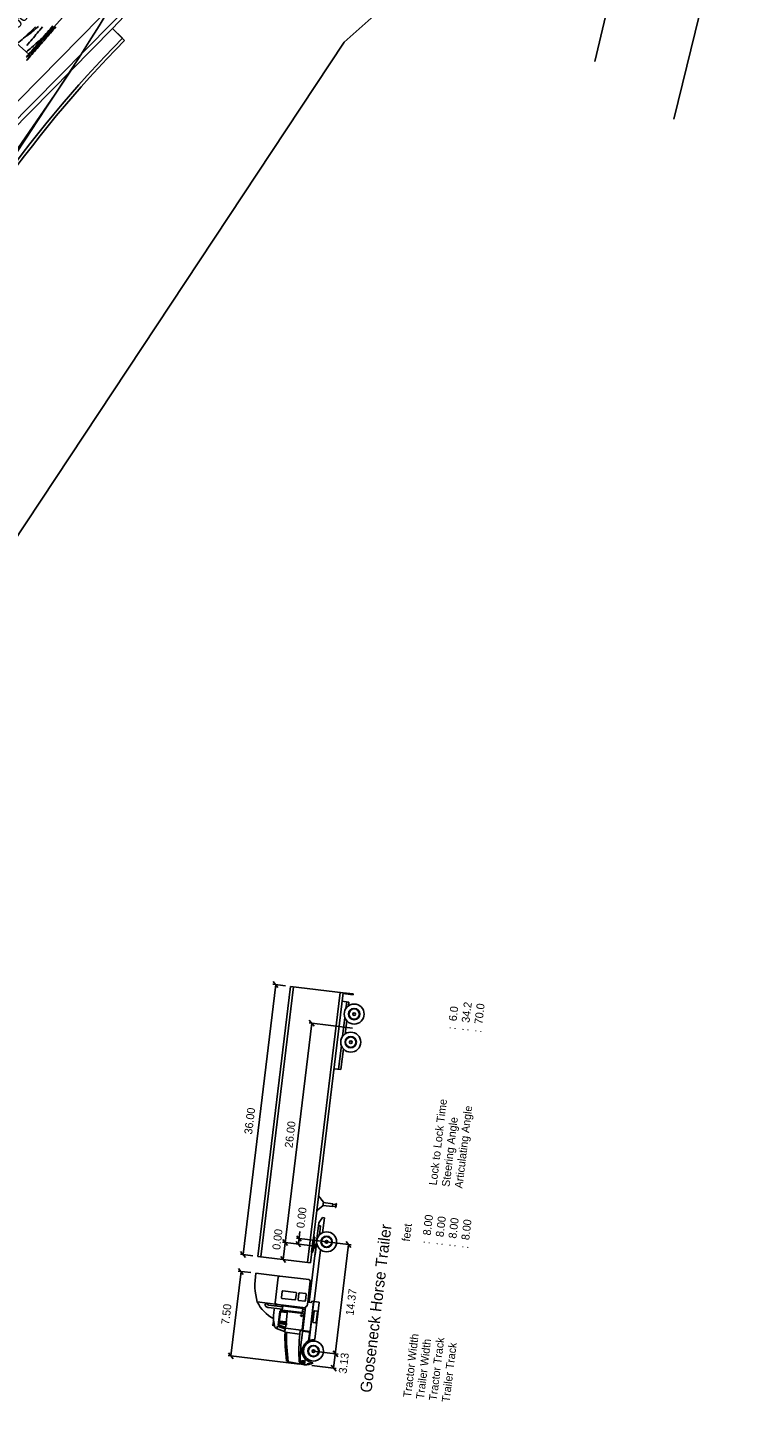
# Model space of a CAD drawing. Extents: x -14 to 1565148, y -25 to 642856.
# Drawn here: x 1564862.1 to 1564980.6, y 636183.8 to 636409.1 of the extents above; entities that cross this region are included whole.
import ezdxf

# ---------------------------------------------------------------- set-up
doc = ezdxf.new("R2010")
doc.units = 0
for name, color, linetype in [('DR_P_Erosion_Control', 7, 'Continuous'), ('DR_P_Headwall', 7, 'Continuous'), ('GE_X_Alignment', 7, 'Continuous'), ('MT_P_Drums', 7, 'Continuous'), ('PF_P_Grade_Line', 7, 'Continuous'), ('PM_P_Edge_Line', 7, 'Continuous'), ('PV_P_EOP', 7, 'Continuous'), ('PV_P_Saw_Cut_Line', 7, 'Continuous'), ('PV_X_EOP', 7, 'Continuous'), ('SC_Scratch2', 7, 'Continuous'), ('TR_Turning_Path23', 7, 'Continuous'), ('TR_Turning_Path25', 7, 'Continuous'), ('TR_Turning_Path27', 7, 'Continuous'), ('TR_Turning_Path28', 7, 'Continuous')]:
    doc.layers.add(name, color=color, linetype=linetype)

msp = doc.modelspace()

# ---------------------------------------------------------------- linework, layer by layer
at = {"layer": 'DR_P_Erosion_Control'}
for points in [[(1564881.8, 636423.67), (1564881.06, 636422.17), (1564879.75, 636419.64), (1564878.38, 636417.1), (1564876.93, 636414.54), (1564875.42, 636411.96), (1564873.86, 636409.38), (1564872.24, 636406.8), (1564870.59, 636404.2), (1564868.91, 636401.61), (1564867.2, 636399.01), (1564865.44, 636396.36), (1564863.66, 636393.67), (1564861.88, 636390.97), (1564860.09, 636388.25), (1564858.31, 636385.51), (1564857.43, 636384.14)], [(1564869.82, 636402.93), (1564868.42, 636400.82), (1564866.64, 636398.18), (1564864.84, 636395.55), (1564863.03, 636392.92), (1564861.23, 636390.3), (1564859.44, 636387.7), (1564857.68, 636385.12), (1564855.93, 636382.52), (1564854.2, 636379.89), (1564852.49, 636377.24), (1564851.99, 636376.44)]]:
    msp.add_lwpolyline(points, dxfattribs=at)
at = {"layer": 'DR_P_Headwall'}
msp.add_line((1564968.16, 636394.09), (1564980.6, 636444.84), dxfattribs=at)
at = {"layer": 'GE_X_Alignment'}
msp.add_lwpolyline([(1564859.34, 636391.97), (1564876.08, 636408.94), (1564877.69, 636407.36)], dxfattribs=at)
msp.add_arc((1565016.49, 636270.39), 195, 135.3822, 155.0629, dxfattribs=at)
at = {"layer": 'MT_P_Drums'}
for points in [[(1564860.2, 636406.31), (1564860.45, 636406.51), (1564860.71, 636406.73), (1564860.97, 636406.94), (1564861.22, 636407.16), (1564861.48, 636407.38), (1564861.73, 636407.61), (1564861.98, 636407.83), (1564862.23, 636408.06), (1564862.48, 636408.3), (1564862.72, 636408.53), (1564862.97, 636408.77), (1564863.2, 636409.01), (1564863.44, 636409.25)], [(1564861.94, 636404.32), (1564862.16, 636404.57), (1564862.38, 636404.82), (1564862.59, 636405.07), (1564862.81, 636405.32), (1564863.03, 636405.58), (1564863.24, 636405.83), (1564863.46, 636406.08), (1564863.68, 636406.33), (1564863.89, 636406.59), (1564864.11, 636406.84), (1564864.33, 636407.09), (1564864.55, 636407.35), (1564864.76, 636407.6), (1564864.98, 636407.85), (1564865.2, 636408.11), (1564865.41, 636408.36), (1564865.63, 636408.61), (1564865.85, 636408.87), (1564866.06, 636409.12), (1564866.28, 636409.38)]]:
    msp.add_lwpolyline(points, dxfattribs=at)
at = {"layer": 'PF_P_Grade_Line'}
for p, q in [((1564902.84, 636252.15), (1564897.48, 636207.86)), ((1564905.28, 636251.85), (1564899.92, 636207.57)), ((1564905.74, 636251.8), (1564900.38, 636207.51)), ((1564904.46, 636251.95), (1564902.4, 636252.2)), ((1564903.22, 636251.66), (1564902.45, 636252.64)), ((1564913.89, 636250.81), (1564905.28, 636251.85)), ((1564908.07, 636206.58), (1564913.43, 636250.87)), ((1564908.53, 636206.53), (1564913.89, 636250.81)), ((1564914.87, 636249.28), (1564913.72, 636249.42)), ((1564915.56, 636250.45), (1564913.87, 636250.66)), ((1564913.89, 636250.81), (1564915.58, 636250.61)), ((1564914.36, 636248.22), (1564914.49, 636249.32)), ((1564914.8, 636248.67), (1564914.87, 636249.28)), ((1564915.58, 636250.61), (1564915.56, 636250.45)), ((1564913.8, 636243.61), (1564914.18, 636246.76)), ((1564908.75, 636245.82), (1564904.06, 636207.07)), ((1564908.31, 636245.87), (1564915.44, 636245.01)), ((1564909.13, 636245.32), (1564908.36, 636246.31)), ((1564914.24, 636244.06), (1564914.5, 636246.22)), ((1564913.15, 636238.25), (1564913.62, 636242.15)), ((1564913.54, 636238.21), (1564913.95, 636241.6)), ((1564913.54, 636238.21), (1564912.38, 636238.35)), ((1564910.67, 636216.47), (1564909.86, 636217.5)), ((1564910.6, 636215.85), (1564909.56, 636215.04)), ((1564910.6, 636215.85), (1564910.67, 636216.47)), ((1564912.15, 636215.74), (1564910.61, 636215.93)), ((1564912.2, 636216.2), (1564910.66, 636216.39)), ((1564912.15, 636215.74), (1564912.2, 636216.2)), ((1564912.67, 636215.76), (1564912.15, 636215.82)), ((1564912.71, 636216.06), (1564912.19, 636216.13)), ((1564912.65, 636215.6), (1564912.72, 636216.22)), ((1564912.73, 636215.59), (1564912.65, 636215.6)), ((1564912.8, 636216.21), (1564912.72, 636216.22)), ((1564912.73, 636215.59), (1564912.8, 636216.21)), ((1564908.36, 636200.04), (1564909.94, 636213.09)), ((1564909.94, 636213.09), (1564910.54, 636213.94)), ((1564910.53, 636211.44), (1564910.83, 636213.9)), ((1564910.83, 636213.9), (1564910.54, 636213.94)), ((1564906.23, 636210.55), (1564915.25, 636209.46)), ((1564907.03, 636210.05), (1564906.32, 636210.94)), ((1564906.56, 636209.57), (1564906.81, 636211.65)), ((1564908.96, 636210.06), (1564909.22, 636210.73)), ((1564909.12, 636209.54), (1564909.26, 636210.72)), ((1564909.31, 636207.84), (1564909.64, 636210.61)), ((1564909.88, 636212.6), (1564910.19, 636212.57)), ((1564910.01, 636211.07), (1564910.19, 636212.57)), ((1564897.87, 636207.37), (1564897.09, 636208.36)), ((1564908.87, 636209.29), (1564903.95, 636209.89)), ((1564904.78, 636209.34), (1564904.01, 636210.33)), ((1564906.91, 636209.12), (1564906.21, 636210.02)), ((1564908.74, 636208.25), (1564908.96, 636210.06)), ((1564908.86, 636209.22), (1564908.99, 636209.2)), ((1564908.88, 636209.37), (1564909.01, 636209.36)), ((1564908.96, 636208.23), (1564909.05, 636209)), ((1564908.99, 636209.2), (1564909.01, 636209.36)), ((1564909.18, 636209.02), (1564909.12, 636209.11)), ((1564909.24, 636209.49), (1564909.16, 636209.41)), ((1564909.17, 636200.17), (1564910.2, 636208.66)), ((1564909.18, 636209), (1564909.2, 636209.16)), ((1564909.42, 636208.79), (1564909.19, 636208.97)), ((1564909.24, 636209.51), (1564909.22, 636209.34)), ((1564909.53, 636209.65), (1564909.26, 636209.54)), ((1564912.35, 636189.22), (1564914.81, 636209.51)), ((1564915.2, 636209.02), (1564914.42, 636210.01)), ((1564899.11, 636207.67), (1564897.04, 636207.92)), ((1564908.53, 636206.53), (1564899.92, 636207.57)), ((1564904.45, 636206.58), (1564903.67, 636207.56)), ((1564908.74, 636208.25), (1564908.96, 636208.23)), ((1564897.15, 636205.1), (1564895.47, 636191.26)), ((1564898.77, 636204.9), (1564896.71, 636205.15)), ((1564897.53, 636204.6), (1564896.76, 636205.59)), ((1564903.51, 636204.33), (1564899.6, 636204.8)), ((1564902.75, 636199.97), (1564903.25, 636204.13)), ((1564903.51, 636204.33), (1564908.31, 636203.75)), ((1564903.77, 636200.81), (1564903.89, 636201.82)), ((1564906.14, 636201.66), (1564904.01, 636201.92)), ((1564906.12, 636200.52), (1564906.24, 636201.54)), ((1564907.77, 636201.46), (1564906.76, 636201.58)), ((1564908.1, 636200.07), (1564908.51, 636203.49)), ((1564903.22, 636199.68), (1564899.82, 636200.09)), ((1564901.48, 636199.76), (1564901.09, 636199.81)), ((1564903.97, 636199.28), (1564901.72, 636199.55)), ((1564903.22, 636199.68), (1564902.95, 636199.71)), ((1564903.22, 636199.68), (1564907.73, 636199.14)), ((1564903.74, 636199.31), (1564903.78, 636199.61)), ((1564905.99, 636200.43), (1564903.86, 636200.68)), ((1564903.91, 636198.74), (1564903.99, 636199.43)), ((1564907.28, 636199.03), (1564903.99, 636199.43)), ((1564906.51, 636200.47), (1564906.63, 636201.49)), ((1564907.62, 636200.23), (1564906.61, 636200.35)), ((1564907.75, 636199.28), (1564907.28, 636195.39)), ((1564907.73, 636199.14), (1564907.75, 636199.28)), ((1564907.74, 636200.32), (1564907.87, 636201.34)), ((1564907.87, 636199.37), (1564907.9, 636199.37)), ((1564908.02, 636199.46), (1564908.1, 636200.07)), ((1564908.1, 636200.07), (1564908.63, 636200)), ((1564908.34, 636193.77), (1564909.12, 636200.18)), ((1564908.48, 636195.29), (1564909.07, 636200.18)), ((1564908.78, 636200.12), (1564908.8, 636200.22)), ((1564908.8, 636200.22), (1564909.94, 636200.08)), ((1564909.27, 636193.98), (1564910, 636200)), ((1564903.93, 636198.89), (1564901.68, 636199.17)), ((1564902.4, 636197.16), (1564902.49, 636197.15)), ((1564902.49, 636197.08), (1564902.4, 636197.16)), ((1564902.41, 636196.43), (1564902.49, 636197.08)), ((1564903.25, 636196.36), (1564903.51, 636198.5)), ((1564903.37, 636196.39), (1564903.62, 636198.43)), ((1564903.66, 636198.62), (1564903.7, 636198.92)), ((1564907.36, 636198.17), (1564903.66, 636198.62)), ((1564904.68, 636198.37), (1564903.7, 636198.49)), ((1564907.2, 636198.34), (1564903.91, 636198.74)), ((1564904.48, 636196.01), (1564904.75, 636198.29)), ((1564907.02, 636197.97), (1564906.91, 636197.87)), ((1564907, 636197.74), (1564906.91, 636197.87)), ((1564907, 636197.74), (1564907.02, 636197.97)), ((1564907.21, 636197.72), (1564907, 636197.74)), ((1564907.23, 636197.95), (1564907.02, 636197.97)), ((1564907.18, 636195.6), (1564907.48, 636198.02)), ((1564907.2, 636198.34), (1564907.28, 636199.03)), ((1564907.21, 636197.72), (1564907.23, 636197.95)), ((1564907.65, 636198.44), (1564907.22, 636198.5)), ((1564907.69, 636198.83), (1564907.26, 636198.88)), ((1564908.93, 636196.78), (1564909.14, 636198.57)), ((1564909.62, 636198.58), (1564909.22, 636198.63)), ((1564909.46, 636196.71), (1564909.68, 636198.5)), ((1564902.28, 636196.31), (1564902.41, 636196.43)), ((1564902.55, 636196.27), (1564902.28, 636196.31)), ((1564902.49, 636196.42), (1564902.53, 636196.78)), ((1564902.56, 636196.32), (1564902.49, 636196.42)), ((1564902.54, 636196.16), (1564902.58, 636196.51)), ((1564902.67, 636196.14), (1564902.54, 636196.16)), ((1564902.95, 636195.76), (1564902.91, 636195.77)), ((1564904.29, 636195.25), (1564902.95, 636195.76)), ((1564903.04, 636195.72), (1564903.14, 636196.12)), ((1564904.34, 636195.67), (1564903.14, 636196.12)), ((1564903.31, 636196.44), (1564903.35, 636196.76)), ((1564903.34, 636196.43), (1564903.31, 636196.44)), ((1564903.34, 636196.43), (1564903.38, 636196.76)), ((1564904.45, 636195.79), (1564903.34, 636196.21)), ((1564903.39, 636196.56), (1564904.53, 636196.42)), ((1564904.37, 636195.95), (1564903.42, 636196.31)), ((1564903.46, 636196.83), (1564904.54, 636196.7)), ((1564903.47, 636196.85), (1564904.54, 636196.72)), ((1564903.49, 636196.71), (1564903.52, 636196.95)), ((1564904.47, 636196.59), (1564903.49, 636196.71)), ((1564903.52, 636196.95), (1564904.5, 636196.83)), ((1564904.29, 636195.25), (1564904.38, 636195.58)), ((1564904.34, 636195.67), (1564904.39, 636195.81)), ((1564904.38, 636195.12), (1564906.75, 636194.83)), ((1564904.45, 636195.79), (1564907.03, 636195.48)), ((1564904.5, 636196.83), (1564904.47, 636196.59)), ((1564904.61, 636196.61), (1564904.57, 636196.29)), ((1564904.59, 636196.28), (1564904.57, 636196.29)), ((1564904.63, 636196.61), (1564904.59, 636196.28)), ((1564906.83, 636194.89), (1564906.88, 636195.37)), ((1564906.96, 636195.43), (1564907.28, 636195.39)), ((1564907.27, 636195.3), (1564908.42, 636195.16)), ((1564907.28, 636195.39), (1564908.43, 636195.25)), ((1564908.25, 636193.72), (1564908.43, 636195.25)), ((1564909.39, 636196.65), (1564908.99, 636196.7)), ((1564906.76, 636189.89), (1564895.03, 636191.31)), ((1564895.86, 636190.77), (1564895.09, 636191.75)), ((1564907.57, 636189.79), (1564904.74, 636190.32)), ((1564906.87, 636190.08), (1564906.96, 636190.31)), ((1564906.96, 636190.31), (1564907.47, 636190.13)), ((1564907.44, 636189.86), (1564907.5, 636190.37)), ((1564907.57, 636189.79), (1564907.68, 636190.7)), ((1564909.07, 636192.03), (1564913.08, 636191.55)), ((1564913.03, 636191.11), (1564912.26, 636192.09)), ((1564908, 636189.79), (1564908.02, 636189.93)), ((1564908.02, 636189.93), (1564908.47, 636190.02)), ((1564908.45, 636189.87), (1564908.47, 636190.02)), ((1564908.78, 636189.65), (1564912.79, 636189.16)), ((1564912.74, 636188.72), (1564911.97, 636189.71))]:
    msp.add_line(p, q, dxfattribs=at)
for centre, radius in [((1564915.72, 636247.31), 1.64), ((1564915.72, 636247.31), 0.929), ((1564915.72, 636247.31), 0.852), ((1564915.72, 636247.31), 0.223), ((1564915.16, 636242.7), 1.64), ((1564915.16, 636242.7), 0.929), ((1564915.16, 636242.7), 0.852), ((1564915.16, 636242.7), 0.223), ((1564911.2, 636209.95), 1.64), ((1564911.2, 636209.95), 0.929), ((1564911.2, 636209.95), 0.852), ((1564909.08, 636209.27), 0.0483), ((1564911.2, 636209.95), 0.223), ((1564909.04, 636192.04), 1.64), ((1564909.04, 636192.04), 0.929), ((1564909.04, 636192.04), 0.852), ((1564909.04, 636192.04), 0.223)]:
    msp.add_circle(centre, radius, dxfattribs=at)
for centre, radius, start, end in [((1564909.24, 636210.7), 0.0343, 44.2496, 121.9601), ((1564909.21, 636208.98), 0.155, 113.1048, 173.1048), ((1564909.27, 636209.52), 0.155, 173.1048, 233.1048), ((1564909.08, 636209.27), 0.155, 293.1048, 53.1048), ((1564909.22, 636209), 0.0387, 173.1048, 233.1048), ((1564909.28, 636209.5), 0.0387, 113.1048, 173.1048), ((1564909.87, 636202.92), 10.44, 169.6193, 195.7684), ((1564903.48, 636204.1), 0.232, 83.1048, 173.1048), ((1564904, 636201.81), 0.109, 83.1048, 173.1048), ((1564906.13, 636201.55), 0.109, 353.1048, 83.1048), ((1564906.74, 636201.48), 0.109, 83.1048, 173.1048), ((1564908.28, 636203.52), 0.232, 353.1048, 83.1048), ((1564905.14, 636202.66), 5.91, 205.8307, 243.2028), ((1564901.7, 636199.78), 0.614, 177.4065, 267.4065), ((1564901.81, 636199.91), 0.369, 203.6157, 255.7447), ((1564902.98, 636199.94), 0.232, 173.1048, 263.1048), ((1564903.17, 636199.22), 0.465, 83.1048, 153.7642), ((1564903.88, 636200.79), 0.109, 173.1048, 263.1048), ((1564906.01, 636200.53), 0.109, 263.1048, 353.1048), ((1564906.62, 636200.46), 0.109, 173.1048, 263.1048), ((1564907.64, 636200.34), 0.109, 263.1048, 353.1048), ((1564907.86, 636199.27), 0.109, 83.1048, 173.1048), ((1564907.76, 636201.35), 0.109, 353.1048, 83.1048), ((1564907.91, 636199.48), 0.109, 263.1048, 353.1048), ((1564908.65, 636200.14), 0.136, 263.1048, 353.1048), ((1564909.93, 636200.01), 0.0682, 353.1048, 83.1048), ((1564907.52, 636197.52), 5.04, 171.3705, 197.9534), ((1564907.17, 636198.03), 4.64, 167.3148, 176.9795), ((1564903.64, 636198.48), 0.136, 83.1048, 173.1048), ((1564903.69, 636198.42), 0.0774, 83.1048, 173.1048), ((1564904.67, 636198.3), 0.0774, 353.1048, 83.1048), ((1564906.91, 636197.87), 0.00545, 83.1048, 263.1048), ((1564906.91, 636197.87), 0.00545, 263.1048, 83.1048), ((1564907.34, 636198.03), 0.136, 353.1048, 83.1048), ((1564909.21, 636198.56), 0.0682, 83.1048, 173.1048), ((1564909.61, 636198.51), 0.0682, 353.1048, 83.1048), ((1564902.61, 636196.2), 0.0826, 210.2016, 316.008), ((1564903.02, 636196.06), 0.31, 197.9534, 249.2351), ((1564903.39, 636196.34), 0.136, 173.1048, 249.2351), ((1564903.45, 636196.75), 0.101, 83.1048, 173.1048), ((1564903.45, 636196.38), 0.0774, 173.1048, 249.2351), ((1564903.45, 636196.75), 0.0774, 83.1048, 173.1048), ((1564904.24, 636195.12), 0.136, 357.9758, 69.2351), ((1564904.31, 636195.6), 0.0682, 344.917, 69.2351), ((1564930.35, 636194.21), 25.99, 177.9944, 188.338), ((1564904.4, 636196.02), 0.0774, 249.2351, 353.1048), ((1564904.53, 636196.62), 0.101, 353.1048, 83.1048), ((1564904.53, 636196.62), 0.0774, 353.1048, 83.1048), ((1564930.35, 636194.21), 25.74, 178.0423, 188.7563), ((1564932.63, 636191.87), 25.98, 173.3547, 183.582), ((1564906.76, 636194.9), 0.0682, 263.1048, 353.1048), ((1564945.84, 636189.62), 38.99, 171.4929, 178.7582), ((1564906.95, 636195.36), 0.0682, 83.1048, 173.1048), ((1564907.05, 636195.61), 0.136, 263.1048, 353.1048), ((1564908.44, 636195.29), 0.0436, 263.1048, 353.1048), ((1564908.99, 636196.77), 0.0682, 173.1048, 263.1048), ((1564909.4, 636196.72), 0.0682, 263.1048, 353.1048), ((1564909.09, 636192.02), 1.9, 86.7335, 266.1908), ((1564909.2, 636193.99), 0.0682, 267.7296, 353.1048), ((1564904.77, 636190.46), 0.136, 188.2811, 258.1777), ((1564906.62, 636190.47), 0.235, 289.2763, 359.7521), ((1564906.84, 636190.25), 0.136, 183.5422, 240.5722), ((1564907.34, 636189.89), 0.569, 79.5267, 131.6268), ((1564907.43, 636190.38), 0.0682, 353.1048, 79.3801), ((1564908.67, 636193.51), 3.87, 240.5722, 253.5651), ((1564907.83, 636191.82), 2.05, 262.8756, 303.7608)]:
    msp.add_arc(centre, radius, start, end, dxfattribs=at)
at = {"layer": 'PM_P_Edge_Line'}
msp.add_line((1564955.19, 636403.52), (1564963.45, 636437.86), dxfattribs=at)
msp.add_lwpolyline([(1564866.68, 636409.28), (1564866.44, 636409.06), (1564866.2, 636408.85), (1564865.96, 636408.64), (1564865.72, 636408.43), (1564865.47, 636408.22), (1564865.23, 636408.01), (1564864.99, 636407.8), (1564864.75, 636407.59), (1564864.51, 636407.38), (1564864.27, 636407.17), (1564864.03, 636406.96), (1564863.79, 636406.75), (1564863.55, 636406.54), (1564863.31, 636406.33), (1564863.07, 636406.11), (1564862.83, 636405.9), (1564862.59, 636405.69), (1564862.35, 636405.48), (1564862.11, 636405.27), (1564861.88, 636405.05)], dxfattribs=at)
msp.add_arc((1564943.31, 636324.49), 120.22, 121.7704, 146.7121, dxfattribs=at)
at = {"layer": 'PV_P_EOP'}
for p, q in [((1564893.35, 636427.51), (1564858.81, 636392.49)), ((1564876.08, 636408.94), (1564882.93, 636416.23)), ((1564876.08, 636408.94), (1564859.34, 636391.97)), ((1564876.08, 636408.94), (1564878.04, 636407.01))]:
    msp.add_line(p, q, dxfattribs=at)
for radius in [195, 194.5]:
    msp.add_arc((1565016.49, 636270.39), radius, 135.3822, 155.0629, dxfattribs=at)
at = {"layer": 'PV_P_Saw_Cut_Line'}
for p, q in [((1564862.37, 636404.68), (1564886.42, 636431.47)), ((1564856.42, 636410.02), (1564862.37, 636404.68))]:
    msp.add_line(p, q, dxfattribs=at)
msp.add_lwpolyline([(1564861.96, 636404.19), (1564862.18, 636404.44), (1564862.4, 636404.68), (1564862.62, 636404.93), (1564862.84, 636405.18), (1564863.06, 636405.43), (1564863.28, 636405.68), (1564863.5, 636405.92), (1564863.73, 636406.17), (1564863.95, 636406.42), (1564864.17, 636406.67), (1564864.39, 636406.91), (1564864.61, 636407.16), (1564864.83, 636407.41), (1564865.05, 636407.66), (1564865.27, 636407.91), (1564865.5, 636408.15), (1564865.72, 636408.4), (1564865.94, 636408.65), (1564866.16, 636408.9), (1564866.38, 636409.15)], dxfattribs=at)
msp.add_arc((1564910.73, 636345.56), 83.46, 121.5902, 132.6698, dxfattribs=at)
at = {"layer": 'PV_X_EOP'}
msp.add_line((1564891.93, 636428.91), (1564857.38, 636393.89), dxfattribs=at)
at = {"layer": 'SC_Scratch2'}
msp.add_line((1564857.14, 636320.76), (1564914.07, 636406.71), dxfattribs=at)
msp.add_lwpolyline([(1564914.07, 636406.71), (1564919.97, 636411.98), (1564924.8, 636417.23), (1564929.14, 636422.75), (1564933.37, 636428.5), (1564936.96, 636434.73), (1564939.12, 636439.05), (1564940.16, 636441.26), (1564941.76, 636445.7), (1564942.51, 636448.08), (1564943.83, 636452.24), (1564945.43, 636458.75), (1564947.27, 636465.18), (1564948.87, 636471.95), (1564949.97, 636478.8), (1564950.92, 636485.83)], dxfattribs=at)
at = {"layer": 'TR_Turning_Path23'}
msp.add_lwpolyline([(1564862.01, 636406.19), (1564862.22, 636406.44), (1564862.44, 636406.69), (1564862.65, 636406.94), (1564862.86, 636407.19), (1564863.08, 636407.45), (1564863.29, 636407.7), (1564863.5, 636407.95), (1564863.72, 636408.2), (1564863.93, 636408.45), (1564864.15, 636408.7), (1564864.36, 636408.95), (1564864.58, 636409.21)], dxfattribs=at)
msp.add_arc((1564930.46, 636336.22), 104.93, 128.0339, 154.7577, dxfattribs=at)
at = {"layer": 'TR_Turning_Path25'}
for points in [[(1564861.95, 636407.64), (1564862.19, 636407.85), (1564862.44, 636408.06), (1564862.69, 636408.27), (1564862.94, 636408.48), (1564863.19, 636408.69), (1564863.44, 636408.89), (1564863.69, 636409.1), (1564863.94, 636409.3)], [(1564861.95, 636403.7), (1564862.17, 636403.95), (1564862.39, 636404.2), (1564862.61, 636404.45), (1564862.83, 636404.7), (1564863.05, 636404.95), (1564863.26, 636405.2), (1564863.48, 636405.45), (1564863.7, 636405.7), (1564863.92, 636405.95), (1564864.14, 636406.21), (1564864.36, 636406.46), (1564864.58, 636406.71), (1564864.8, 636406.96), (1564865.02, 636407.21), (1564865.24, 636407.46), (1564865.46, 636407.71), (1564865.67, 636407.96), (1564865.89, 636408.21), (1564866.11, 636408.46), (1564866.33, 636408.71), (1564866.55, 636408.97), (1564866.77, 636409.22)]]:
    msp.add_lwpolyline(points, dxfattribs=at)
msp.add_arc((1564940.69, 636314.87), 124.92, 128.0039, 166.2183, dxfattribs=at)
at = {"layer": 'TR_Turning_Path27'}
msp.add_lwpolyline([(1564862.02, 636403.77), (1564862.22, 636404.04), (1564862.42, 636404.3), (1564862.62, 636404.56), (1564862.82, 636404.82), (1564863.02, 636405.09), (1564863.22, 636405.35), (1564863.42, 636405.61), (1564863.62, 636405.88), (1564863.82, 636406.14), (1564864.03, 636406.4), (1564864.23, 636406.66), (1564864.43, 636406.93), (1564864.63, 636407.19), (1564864.83, 636407.45), (1564865.03, 636407.71), (1564865.23, 636407.98), (1564865.44, 636408.24), (1564865.64, 636408.5), (1564865.84, 636408.76), (1564866.04, 636409.02), (1564866.25, 636409.29)], dxfattribs=at)
at = {"layer": 'TR_Turning_Path28'}
msp.add_arc((1564830.37, 636475.45), 67.91, 239.7175, 333.525, dxfattribs=at)

# ---------------------------------------------------------------- texts
at = {"layer": 'PF_P_Grade_Line'}
for s, height, p in [('34.2', 1.312, (1564934.63, 636245.83)), ('70.0', 1.312, (1564936.74, 636245.58)), ('6.0', 1.312, (1564932.52, 636246.09)), (':', 1.31, (1564932.35, 636244.7)), (':', 1.31, (1564934.46, 636244.45)), (':', 1.31, (1564936.57, 636244.19)), ('Lock to Lock Time', 1.3123, (1564929.26, 636219.17)), ('36.00', 1.312, (1564898.96, 636227.51)), ('Articulating Angle', 1.3123, (1564933.48, 636218.66)), ('26.00', 1.312, (1564905.6, 636225.3)), ('Steering Angle', 1.3123, (1564931.37, 636218.91)), ('0.00', 1.312, (1564907.53, 636212.14)), ('Gooseneck Horse Trailer', 1.8701, (1564918.54, 636185.13)), ('feet', 1.312, (1564924.84, 636209.95)), ('8.00', 1.312, (1564928.27, 636210.94)), ('8.00', 1.312, (1564930.38, 636210.68)), ('8.00', 1.312, (1564932.48, 636210.43)), ('8.00', 1.312, (1564934.59, 636210.17)), ('0.00', 1.312, (1564903.57, 636208.58)), (':', 1.31, (1564928.1, 636209.55)), (':', 1.31, (1564930.21, 636209.3)), (':', 1.31, (1564932.32, 636209.04)), (':', 1.31, (1564934.43, 636208.79)), ('14.37', 1.312, (1564915.61, 636197.81)), ('7.50', 1.312, (1564895.19, 636196.3)), ('Tractor Width', 1.3123, (1564925.05, 636184.35)), ('Trailer Width', 1.3123, (1564927.16, 636184.09)), ('Tractor Track', 1.3123, (1564929.27, 636183.84)), ('Trailer Track', 1.3123, (1564931.38, 636183.58)), ('3.13', 1.312, (1564914.46, 636188.28))]:
    msp.add_text(s, height=height, rotation=83.1048, dxfattribs=at).set_placement(p)
at = {"layer": 'PV_P_Saw_Cut_Line'}
msp.add_text('Gooseneck Horse Trailer', height=2, rotation=48.0843, dxfattribs=at).set_placement((1564859.06, 636407.21))

doc.saveas('drawing.dxf')
